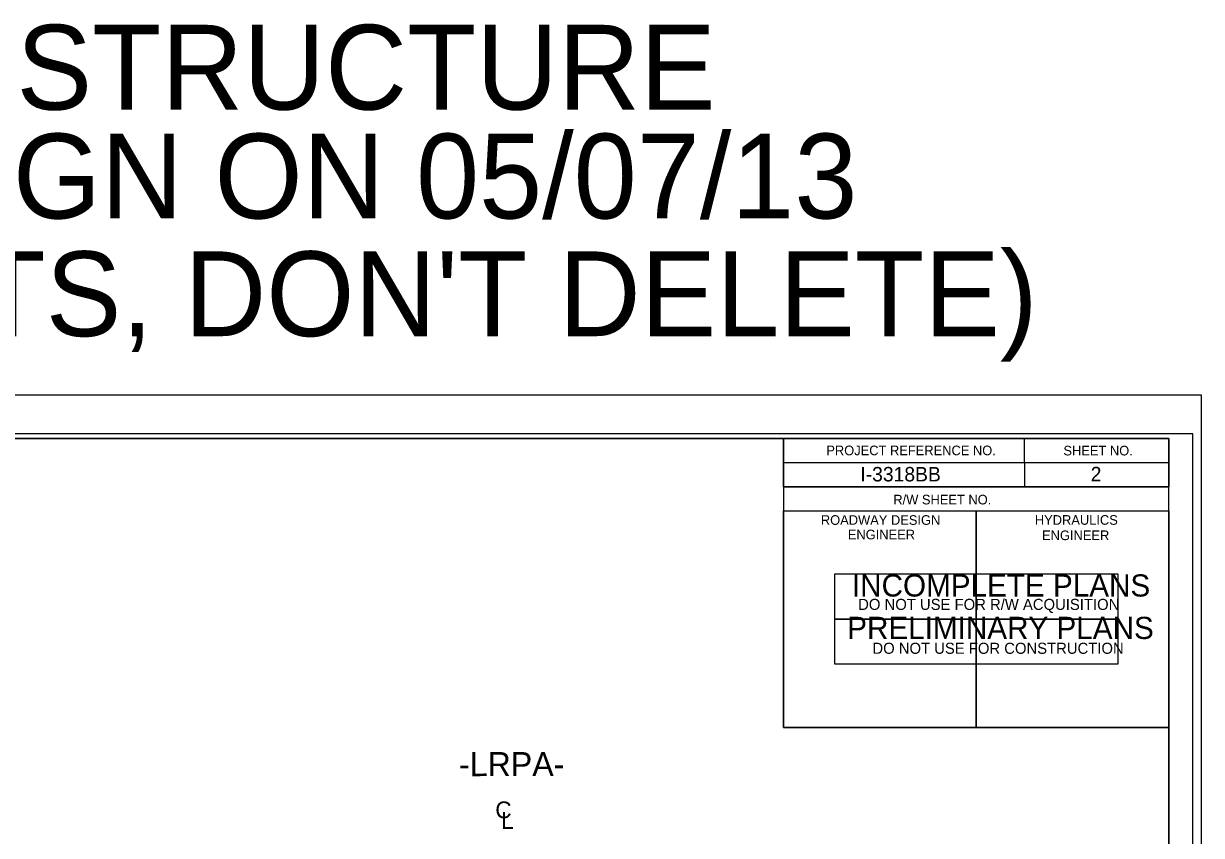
# Model space of a CAD drawing. Extents: x 2241081 to 2251104, y 658534 to 663427.
# Drawn here: x 2243878 to 2244490, y 662609 to 663031 of the extents above; entities that cross this region are included whole.
import ezdxf

# ---------------------------------------------------------------- set-up
doc = ezdxf.new("R2010")
doc.units = 0
for name, color, linetype in [('Prop Dimension Text', 7, 'Continuous'), ('Sheet Cutting Line CELL', 7, 'Continuous'), ('Sheet Data Field CELL', 7, 'Continuous'), ('Sheet Plan CELL', 7, 'Continuous'), ('Sheet Plot Border Inside CELL', 7, 'Continuous'), ('Sheet Plot Border Outside CELL', 7, 'Continuous'), ('Sheet Sticker Incomplete CELL', 7, 'Continuous'), ('Sheet Sticker Preliminary CELL', 7, 'Continuous'), ('Typical Text Centerline CELL', 7, 'Continuous'), ('Typical Text Label CELL', 7, 'Continuous')]:
    doc.layers.add(name, color=color, linetype=linetype)

msp = doc.modelspace()

# ---------------------------------------------------------------- linework, layer by layer
at = {"layer": 'Sheet Cutting Line CELL'}
msp.add_line((2244489.63, 662837.89), (2242806.13, 662837.89), dxfattribs=at)
at = {"layer": 'Sheet Plan CELL'}
for p, q in [((2244397.59, 662815.34), (2244397.64, 662790.34)), ((2244272.57, 662802.87), (2244472.62, 662802.85)), ((2244272.58, 662790.33), (2244472.62, 662790.35)), ((2244272.58, 662790.33), (2244472.62, 662790.35)), ((2244272.58, 662790.33), (2244272.58, 662777.84)), ((2244372.63, 662777.84), (2244372.64, 662665.38))]:
    msp.add_line(p, q, dxfattribs=at)
for points in [[(2242972.61, 661765.4), (2242972.59, 662815.38), (2244272.58, 662815.42), (2244272.59, 662665.35), (2244472.63, 662665.34), (2244472.63, 661765.4)], [(2244472.65, 662815.4), (2242972.62, 662815.4), (2242972.61, 661765.4), (2244472.63, 661765.4)], [(2244272.58, 662815.42), (2244472.65, 662815.4), (2244472.62, 662790.35), (2244272.58, 662790.33)], [(2244272.58, 662777.84), (2244372.63, 662777.84), (2244372.63, 662665.33), (2244272.59, 662665.35)], [(2244372.63, 662777.84), (2244472.62, 662777.85), (2244472.63, 662665.34), (2244372.63, 662665.33)]]:
    msp.add_lwpolyline(points, close=True, dxfattribs=at)
at = {"layer": 'Sheet Plot Border Inside CELL'}
msp.add_lwpolyline([(2242819.13, 661762.89), (2244485.11, 661762.9), (2244485.13, 662817.89), (2242819.13, 662817.89)], close=True, dxfattribs=at)
at = {"layer": 'Sheet Plot Border Outside CELL'}
msp.add_lwpolyline([(2242806.13, 661742.89), (2244489.63, 661742.89), (2244489.63, 662837.89), (2242806.13, 662837.89)], close=True, dxfattribs=at)
at = {"layer": 'Sheet Sticker Incomplete CELL'}
msp.add_lwpolyline([(2244299.13, 662721.59), (2244299.13, 662745.09), (2244446.13, 662745.09), (2244446.13, 662721.59)], close=True, dxfattribs=at)
at = {"layer": 'Sheet Sticker Preliminary CELL'}
msp.add_lwpolyline([(2244299.13, 662698.09), (2244299.13, 662721.59), (2244446.13, 662721.59), (2244446.13, 662698.09)], close=True, dxfattribs=at)

# ---------------------------------------------------------------- texts
at = {"layer": 'Prop Dimension Text'}
msp.add_text('-LRPA-', height=12.5, rotation=0.03489, dxfattribs=at).set_placement((2244103.96, 662639.99))
at = {"layer": 'Sheet Data Field CELL'}
for s, p in [('I-3318BB', (2244312.45, 662793.09)), ('2', (2244432.1, 662793.15))]:
    msp.add_text(s, height=7.5, rotation=359.99994, dxfattribs=at).set_placement(p)
at = {"layer": 'Sheet Plan CELL'}
for s, height, p in [('PROJECT REFERENCE NO.', 5.0001, (2244294.78, 662806.69)), ('SHEET NO.', 5, (2244417.94, 662806.58)), ('R/W SHEET NO.', 5.0001, (2244329.58, 662781.14)), ('ROADWAY DESIGN', 5.0001, (2244291.95, 662770.54)), ('HYDRAULICS', 5, (2244403.09, 662770.57)), ('ENGINEER', 5, (2244305.94, 662763)), ('ENGINEER', 5, (2244406.85, 662762.6))]:
    msp.add_text(s, height=height, rotation=359.99994, dxfattribs=at).set_placement(p)
at = {"layer": 'Sheet Sticker Incomplete CELL'}
for s, height, p in [('INCOMPLETE PLANS', 11.52, (2244308.08, 662733.29)), ('DO NOT USE FOR R/W ACQUISITION', 5.76, (2244311.33, 662726.34))]:
    msp.add_text(s, height=height, rotation=359.99993, dxfattribs=at).set_placement(p)
at = {"layer": 'Sheet Sticker Preliminary CELL'}
for s, height, p in [('PRELIMINARY PLANS', 11.52, (2244305.63, 662711.24)), ('DO NOT USE FOR CONSTRUCTION', 5.76, (2244318.73, 662703.54))]:
    msp.add_text(s, height=height, rotation=359.99993, dxfattribs=at).set_placement(p)
at = {"layer": 'Typical Text Centerline CELL'}
for s, rotation, p in [('C', 0.03489, (2244122.84, 662618.1)), ('L', 359.98179, (2244125.87, 662612.6))]:
    msp.add_text(s, height=8.76, rotation=rotation, dxfattribs=at).set_placement(p)
at = {"layer": 'Typical Text Label CELL'}
for s, p in [('TYPICAL APPROACHING STRUCTURE', (2243160.68, 662986.2)), ('AS SENT TO STRUCTURE DESIGN ON 05/07/13', (2242988.76, 662929.67)), ("(NOT PART OF TYPICAL SHEETS, DON'T DELETE)", (2242999.27, 662868.53))]:
    msp.add_text(s, height=44.0423, dxfattribs=at).set_placement(p)

doc.saveas('drawing.dxf')
